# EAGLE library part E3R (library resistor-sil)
SIL RESISTOR
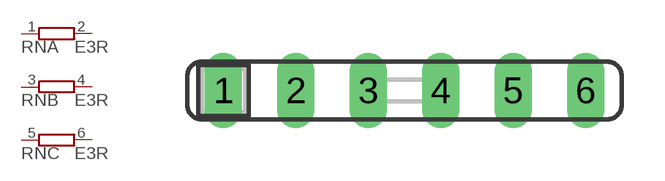
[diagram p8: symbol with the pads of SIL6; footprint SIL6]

Designator prefix RN; gates A=RNV B=RNV C=RNV

## E3R (OC_FARNELL: unknown; OC_NEWARK: unknown)  [SIL6]
1  A:1  pas
2  A:2  pas
3  B:1  pas
4  B:2  pas
5  C:1  pas
6  C:2  pas

## Footprint SIL6 (pad centres in mm)
Single In Line
drill 0.813 long: 1 -6.35,0; 2 -3.81,0; 3 -1.27,0; 4 1.27,0; 5 3.81,0; 6 6.35,0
